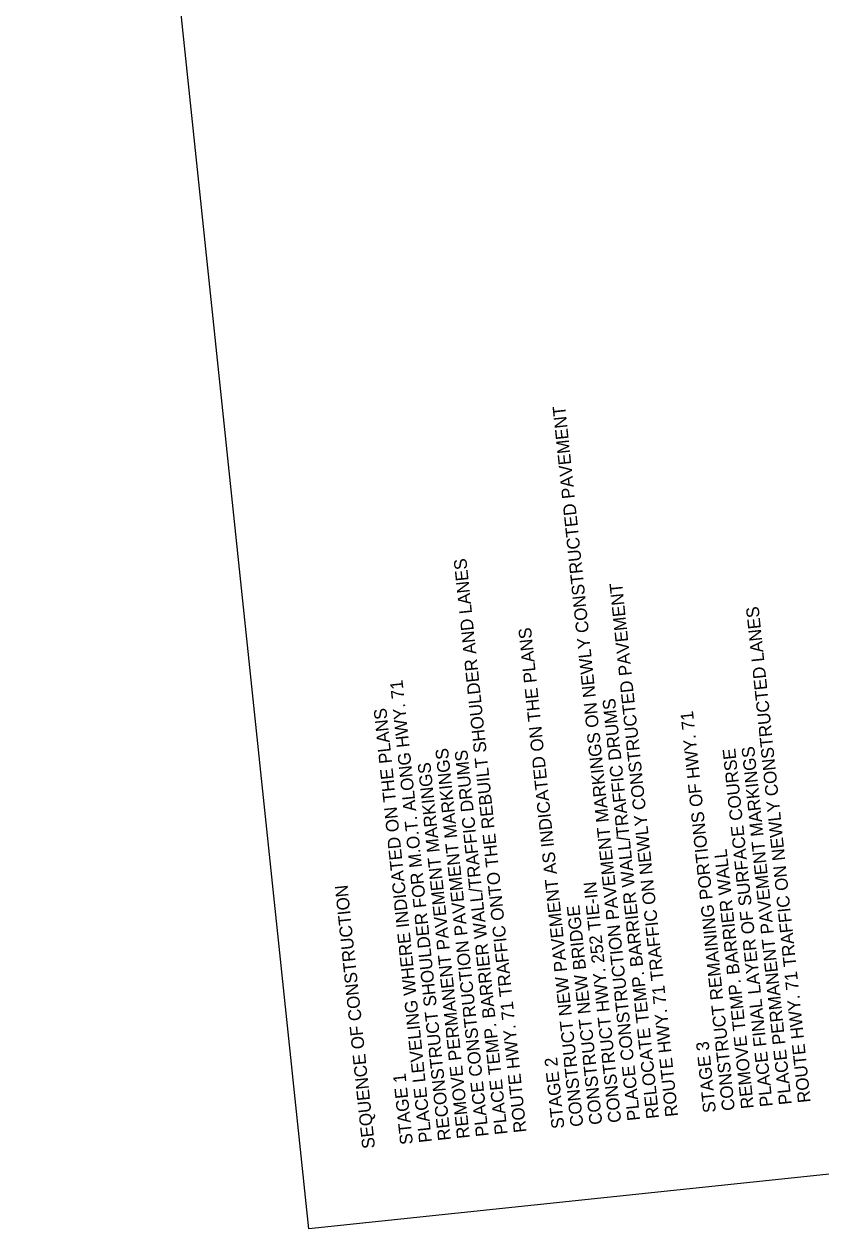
# Model space of a CAD drawing. Extents: x 633427 to 634998, y 288285 to 294065.
# Drawn here: x 633842 to 634219, y 288285 to 288854 of the extents above; entities that cross this region are included whole.
import ezdxf

# ---------------------------------------------------------------- set-up
doc = ezdxf.new("R2010")
doc.units = 0
doc.layers.add('R_50 Horz Alg Ticks', color=7, linetype='Continuous')
doc.layers.add('S_BASELINE', color=7, linetype='Continuous')

msp = doc.modelspace()

# ---------------------------------------------------------------- linework, layer by layer
at = {"layer": 'S_BASELINE'}
msp.add_lwpolyline([(634998.31, 288392.03), (633976.91, 288284.67), (633842.35, 289564.97), (633891.2, 289570.11), (633858.46, 289881.59), (634831, 289983.81)], close=True, dxfattribs=at)

# ---------------------------------------------------------------- texts
at = {"layer": 'R_50 Horz Alg Ticks'}
for s, p in [('PLACE CONSTRUCTION PAVEMENT MARKINGS ON NEWLY CONSTRUCTED PAVEMENT', (634133.53, 288336.09)), ('ROUTE HWY. 71 TRAFFIC ONTO THE REBUILT SHOULDER AND LANES', (634079.82, 288330.45)), ('ROUTE HWY. 71 TRAFFIC ON NEWLY CONSTRUCTED PAVEMENT', (634151.43, 288337.97)), ('ROUTE HWY. 71 TRAFFIC ON NEWLY CONSTRUCTED LANES', (634214.08, 288344.56)), ('CONSTRUCT NEW PAVEMENT AS INDICATED ON THE PLANS', (634106.67, 288333.27)), ('RECONSTRUCT SHOULDER FOR M.O.T. ALONG HWY. 71', (634044.02, 288326.68)), ('RELOCATE TEMP. BARRIER WALL/TRAFFIC DRUMS', (634142.48, 288337.03)), ('PLACE LEVELING WHERE INDICATED ON THE PLANS', (634035.07, 288325.74)), ('CONSTRUCT REMAINING PORTIONS OF HWY. 71', (634178.28, 288340.8)), ('PLACE CONSTRUCTION PAVEMENT MARKINGS', (634061.92, 288328.57)), ('PLACE TEMP. BARRIER WALL/TRAFFIC DRUMS', (634070.87, 288329.51)), ('PLACE FINAL LAYER OF SURFACE COURSE', (634196.18, 288342.68)), ('PLACE PERMANENT PAVEMENT MARKINGS', (634205.13, 288343.62)), ('REMOVE PERMANENT PAVEMENT MARKINGS', (634052.97, 288327.63)), ('REMOVE TEMP. BARRIER WALL', (634187.23, 288341.74)), ('SEQUENCE OF CONSTRUCTION', (634008.22, 288322.92)), ('CONSTRUCT HWY. 252 TIE-IN', (634124.58, 288335.15)), ('CONSTRUCT NEW BRIDGE', (634115.62, 288334.21)), ('STAGE 3', (634169.33, 288339.86)), ('STAGE 2', (634097.72, 288332.33)), ('STAGE 1', (634026.12, 288324.8))]:
    msp.add_text(s, height=6, rotation=96, dxfattribs=at).set_placement(p)

doc.saveas('drawing.dxf')
